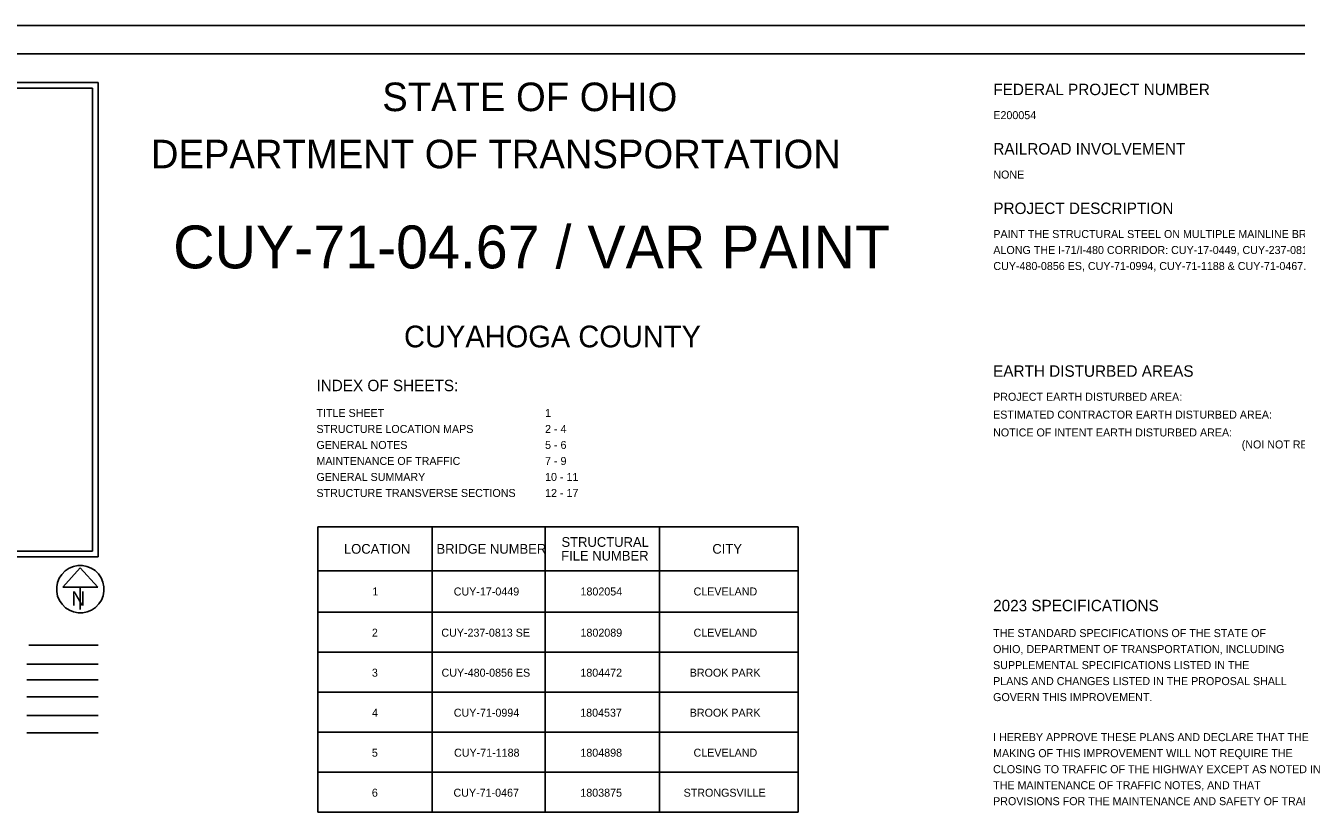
# Model space of a CAD drawing. Extents: x -10 to 89.7, y -4.8 to 22.
# Drawn here: x 7.72 to 29.97, y 8.23 to 22 of the extents above; entities that cross this region are included whole.
import ezdxf

# ---------------------------------------------------------------- set-up
doc = ezdxf.new("R2010")
doc.units = 0
for name, color, linetype in [('GM_X_Minor_Lake', 7, 'Continuous'), ('GM_X_Minor_River', 7, 'Continuous'), ('GM_X_Minor_River_Text', 7, 'Continuous'), ('SH_Text', 7, 'Continuous')]:
    doc.layers.add(name, color=color, linetype=linetype)

msp = doc.modelspace()

# ---------------------------------------------------------------- linework, layer by layer
at = {"layer": 'GM_X_Minor_Lake'}
for p, q in [((2, 21), (9, 21)), ((9, 21), (9, 12.701)), ((2.1, 20.9), (8.9, 20.9)), ((8.9, 20.9), (8.9, 12.801)), ((12.842, 8.235), (12.842, 13.227)), ((12.842, 13.227), (21.245, 13.227)), ((14.842, 8.235), (14.842, 13.227)), ((16.817, 8.235), (16.817, 13.227)), ((18.817, 8.235), (18.817, 13.227)), ((21.245, 8.235), (21.245, 13.227)), ((2, 12.701), (9, 12.701)), ((2.1, 12.801), (8.9, 12.801)), ((8.685, 12.51), (8.377, 12.169)), ((8.992, 12.169), (8.685, 12.51)), ((12.842, 12.456), (21.245, 12.456)), ((8.377, 12.169), (8.992, 12.169)), ((8.685, 12.169), (8.685, 11.782)), ((8.685, 12.136), (8.685, 12.136)), ((8.685, 12.136), (8.685, 12.136)), ((12.842, 11.735), (21.245, 11.735)), ((7.783, 11.156), (9, 11.156)), ((12.842, 11.035), (21.245, 11.035)), ((9, 10.822), (7.75, 10.822)), ((9, 10.55), (7.75, 10.55)), ((9, 10.25), (7.75, 10.25)), ((12.842, 10.335), (21.245, 10.335)), ((9, 9.923), (7.75, 9.923)), ((9, 9.623), (7.75, 9.623)), ((12.842, 9.635), (21.245, 9.635)), ((12.842, 8.935), (21.245, 8.935)), ((12.842, 8.235), (21.245, 8.235))]:
    msp.add_line(p, q, dxfattribs=at)
msp.add_arc((8.685, 12.136), 0.415, 129.7798, 129.7633, dxfattribs=at)
at = {"layer": 'GM_X_Minor_River'}
msp.add_lwpolyline([(1.5, 21.5), (33.5, 21.5), (33.5, 0.5), (1.5, 0.5)], close=True, dxfattribs=at)
at = {"layer": 'SH_Text'}
msp.add_lwpolyline([(0, 0), (34, 0), (34, 22), (0, 22)], close=True, dxfattribs=at)

# ---------------------------------------------------------------- texts
at = {"layer": 'GM_X_Minor_Lake'}
msp.add_text('N', height=0.25, dxfattribs=at).set_placement((8.529, 11.845))
at = {"layer": 'GM_X_Minor_River_Text'}
for s, height, p in [('STATE OF OHIO', 0.5, (13.968, 20.5)), ('FEDERAL PROJECT NUMBER', 0.2, (24.66, 20.78)), ('E200054', 0.14, (24.66, 20.36)), ('DEPARTMENT OF TRANSPORTATION', 0.5, (9.92, 19.5)), ('RAILROAD INVOLVEMENT', 0.2, (24.66, 19.741)), ('NONE', 0.14, (24.66, 19.32)), ('PROJECT DESCRIPTION', 0.2, (24.66, 18.7)), ('CUY-71-04.67 / VAR PAINT', 0.75, (10.31, 17.749)), ('PAINT THE STRUCTURAL STEEL ON MULTIPLE MAINLINE BRIDGES ', 0.14, (24.66, 18.28)), ('ALONG THE I-71/I-480 CORRIDOR: CUY-17-0449, CUY-237-0813 SE,', 0.14, (24.66, 18)), ('CUY-480-0856 ES, CUY-71-0994, CUY-71-1188 & CUY-71-0467.', 0.14, (24.66, 17.72)), ('CUYAHOGA COUNTY', 0.38, (14.349, 16.367)), ('EARTH DISTURBED AREAS', 0.2, (24.656, 15.852)), ('INDEX OF SHEETS:', 0.2, (12.817, 15.6)), ('PROJECT EARTH DISTURBED AREA:', 0.14, (24.656, 15.432)), ('TITLE SHEET', 0.14, (12.817, 15.149)), ('1', 0.14, (16.817, 15.149)), ('ESTIMATED CONTRACTOR EARTH DISTURBED AREA:', 0.14, (24.656, 15.12)), ('STRUCTURE LOCATION MAPS', 0.14, (12.817, 14.869)), ('2 - 4', 0.14, (16.817, 14.869)), ('NOTICE OF INTENT EARTH DISTURBED AREA:', 0.14, (24.656, 14.808)), ('GENERAL NOTES', 0.14, (12.817, 14.589)), ('5 - 6', 0.14, (16.817, 14.589)), ('(NOI NOT REQUIRED)', 0.14, (29.006, 14.598)), ('MAINTENANCE OF TRAFFIC', 0.14, (12.817, 14.309)), ('7 - 9', 0.14, (16.817, 14.309)), ('GENERAL SUMMARY', 0.14, (12.817, 14.029)), ('10 - 11', 0.14, (16.817, 14.029)), ('STRUCTURE TRANSVERSE SECTIONS', 0.14, (12.817, 13.749)), ('12 - 17', 0.14, (16.817, 13.749)), ('LOCATION', 0.17, (13.298, 12.756)), ('BRIDGE NUMBER', 0.17, (14.918, 12.756)), ('STRUCTURAL', 0.17, (17.104, 12.876)), ('CITY', 0.17, (19.744, 12.756)), ('FILE NUMBER', 0.17, (17.099, 12.636)), ('1', 0.14, (13.795, 12.025)), ('CUY-17-0449', 0.14, (15.219, 12.025)), ('1802054', 0.14, (17.437, 12.025)), ('CLEVELAND', 0.14, (19.415, 12.025)), ('2023 SPECIFICATIONS', 0.2, (24.656, 11.749)), ('2', 0.14, (13.787, 11.304)), ('CUY-237-0813 SE', 0.14, (15.002, 11.304)), ('1802089', 0.14, (17.437, 11.304)), ('CLEVELAND', 0.14, (19.415, 11.304)), ('THE STANDARD SPECIFICATIONS OF THE STATE OF', 0.14, (24.656, 11.297)), ('OHIO, DEPARTMENT OF TRANSPORTATION, INCLUDING', 0.14, (24.656, 11.017)), ('3', 0.14, (13.787, 10.604)), ('CUY-480-0856 ES', 0.14, (15.006, 10.604)), ('1804472', 0.14, (17.435, 10.604)), ('BROOK PARK', 0.14, (19.348, 10.604)), ('SUPPLEMENTAL SPECIFICATIONS LISTED IN THE', 0.14, (24.656, 10.737)), ('PLANS AND CHANGES LISTED IN THE PROPOSAL SHALL', 0.14, (24.656, 10.457)), ('GOVERN THIS IMPROVEMENT.', 0.14, (24.656, 10.177)), ('4', 0.14, (13.789, 9.904)), ('CUY-71-0994', 0.14, (15.22, 9.904)), ('1804537', 0.14, (17.432, 9.904)), ('BROOK PARK', 0.14, (19.348, 9.904)), ('I HEREBY APPROVE THESE PLANS AND DECLARE THAT THE ', 0.14, (24.656, 9.476)), ('5', 0.14, (13.786, 9.204)), ('CUY-71-1188', 0.14, (15.225, 9.204)), ('1804898', 0.14, (17.435, 9.204)), ('CLEVELAND', 0.14, (19.415, 9.204)), ('MAKING OF THIS IMPROVEMENT WILL NOT REQUIRE THE ', 0.14, (24.656, 9.196)), ('CLOSING TO TRAFFIC OF THE HIGHWAY EXCEPT AS NOTED IN ', 0.14, (24.656, 8.916)), ('THE MAINTENANCE OF TRAFFIC NOTES, AND THAT ', 0.14, (24.656, 8.636)), ('6', 0.14, (13.786, 8.504)), ('CUY-71-0467', 0.14, (15.215, 8.504)), ('1803875', 0.14, (17.434, 8.504)), ('STRONGSVILLE', 0.14, (19.241, 8.504)), ('PROVISIONS FOR THE MAINTENANCE AND SAFETY OF TRAFFIC ', 0.14, (24.656, 8.356))]:
    msp.add_text(s, height=height, dxfattribs=at).set_placement(p)

doc.saveas('drawing.dxf')
